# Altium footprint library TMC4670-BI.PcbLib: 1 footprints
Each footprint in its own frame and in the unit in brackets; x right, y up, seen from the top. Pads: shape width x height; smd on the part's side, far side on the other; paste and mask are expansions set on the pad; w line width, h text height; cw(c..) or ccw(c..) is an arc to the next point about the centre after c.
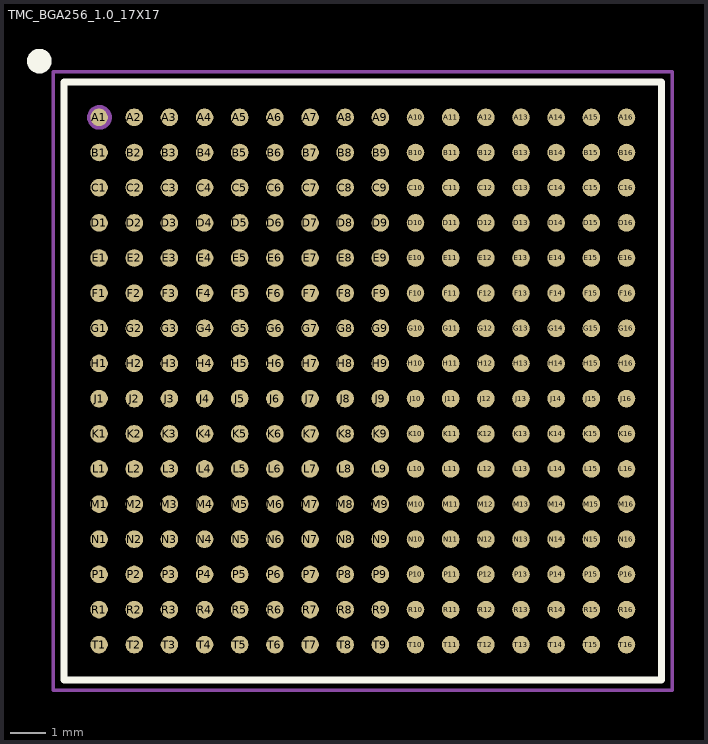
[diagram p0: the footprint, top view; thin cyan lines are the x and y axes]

## TMC_BGA256_1.0_17X17 [mm]
height 2.2
pads (256):
  round 0.5 smd: A1(-1023.5,-1008.5) A2(-1022.5,-1008.5) A3(-1021.5,-1008.5) A4(-1020.5,-1008.5) A5(-1019.5,-1008.5) A6(-1018.5,-1008.5) A7(-1017.5,-1008.5) A8(-1016.5,-1008.5) A9(-1015.5,-1008.5) A10(-1014.5,-1008.5) A11(-1013.5,-1008.5) A12(-1012.5,-1008.5) A13(-1011.5,-1008.5) A14(-1010.5,-1008.5) A15(-1009.5,-1008.5) A16(-1008.5,-1008.5) B1(-1023.5,-1009.5) B2(-1022.5,-1009.5) B3(-1021.5,-1009.5) B4(-1020.5,-1009.5) B5(-1019.5,-1009.5) B6(-1018.5,-1009.5) B7(-1017.5,-1009.5) B8(-1016.5,-1009.5) B9(-1015.5,-1009.5) B10(-1014.5,-1009.5) B11(-1013.5,-1009.5) B12(-1012.5,-1009.5) B13(-1011.5,-1009.5) B14(-1010.5,-1009.5) B15(-1009.5,-1009.5) B16(-1008.5,-1009.5) C1(-1023.5,-1010.5) C2(-1022.5,-1010.5) C3(-1021.5,-1010.5) C4(-1020.5,-1010.5) C5(-1019.5,-1010.5) C6(-1018.5,-1010.5) C7(-1017.5,-1010.5) C8(-1016.5,-1010.5) C9(-1015.5,-1010.5) C10(-1014.5,-1010.5) C11(-1013.5,-1010.5) C12(-1012.5,-1010.5) C13(-1011.5,-1010.5) C14(-1010.5,-1010.5) C15(-1009.5,-1010.5) C16(-1008.5,-1010.5) D1(-1023.5,-1011.5) D2(-1022.5,-1011.5) D3(-1021.5,-1011.5) D4(-1020.5,-1011.5) D5(-1019.5,-1011.5) D6(-1018.5,-1011.5) D7(-1017.5,-1011.5) D8(-1016.5,-1011.5) D9(-1015.5,-1011.5) D10(-1014.5,-1011.5) D11(-1013.5,-1011.5) D12(-1012.5,-1011.5) D13(-1011.5,-1011.5) D14(-1010.5,-1011.5) D15(-1009.5,-1011.5) D16(-1008.5,-1011.5) E1(-1023.5,-1012.5) E2(-1022.5,-1012.5) E3(-1021.5,-1012.5) E4(-1020.5,-1012.5) E5(-1019.5,-1012.5) E6(-1018.5,-1012.5) E7(-1017.5,-1012.5) E8(-1016.5,-1012.5) E9(-1015.5,-1012.5) E10(-1014.5,-1012.5) E11(-1013.5,-1012.5) E12(-1012.5,-1012.5) E13(-1011.5,-1012.5) E14(-1010.5,-1012.5) E15(-1009.5,-1012.5) E16(-1008.5,-1012.5) F1(-1023.5,-1013.5) F2(-1022.5,-1013.5) F3(-1021.5,-1013.5) F4(-1020.5,-1013.5) F5(-1019.5,-1013.5) F6(-1018.5,-1013.5) F7(-1017.5,-1013.5) F8(-1016.5,-1013.5) F9(-1015.5,-1013.5) F10(-1014.5,-1013.5) F11(-1013.5,-1013.5) F12(-1012.5,-1013.5) F13(-1011.5,-1013.5) F14(-1010.5,-1013.5) F15(-1009.5,-1013.5) F16(-1008.5,-1013.5) G1(-1023.5,-1014.5) G2(-1022.5,-1014.5) G3(-1021.5,-1014.5) G4(-1020.5,-1014.5) G5(-1019.5,-1014.5) G6(-1018.5,-1014.5) G7(-1017.5,-1014.5) G8(-1016.5,-1014.5) G9(-1015.5,-1014.5) G10(-1014.5,-1014.5) G11(-1013.5,-1014.5) G12(-1012.5,-1014.5) G13(-1011.5,-1014.5) G14(-1010.5,-1014.5) G15(-1009.5,-1014.5) G16(-1008.5,-1014.5) H1(-1023.5,-1015.5) H2(-1022.5,-1015.5) H3(-1021.5,-1015.5) H4(-1020.5,-1015.5) H5(-1019.5,-1015.5) H6(-1018.5,-1015.5) H7(-1017.5,-1015.5) H8(-1016.5,-1015.5) H9(-1015.5,-1015.5) H10(-1014.5,-1015.5) H11(-1013.5,-1015.5) H12(-1012.5,-1015.5) H13(-1011.5,-1015.5) H14(-1010.5,-1015.5) H15(-1009.5,-1015.5) H16(-1008.5,-1015.5) J1(-1023.5,-1016.5) J2(-1022.5,-1016.5) J3(-1021.5,-1016.5) J4(-1020.5,-1016.5) J5(-1019.5,-1016.5) J6(-1018.5,-1016.5) J7(-1017.5,-1016.5) J8(-1016.5,-1016.5) J9(-1015.5,-1016.5) J10(-1014.5,-1016.5) J11(-1013.5,-1016.5) J12(-1012.5,-1016.5) J13(-1011.5,-1016.5) J14(-1010.5,-1016.5) J15(-1009.5,-1016.5) J16(-1008.5,-1016.5) K1(-1023.5,-1017.5) K2(-1022.5,-1017.5) K3(-1021.5,-1017.5) K4(-1020.5,-1017.5) K5(-1019.5,-1017.5) K6(-1018.5,-1017.5) K7(-1017.5,-1017.5) K8(-1016.5,-1017.5) K9(-1015.5,-1017.5) K10(-1014.5,-1017.5) K11(-1013.5,-1017.5) K12(-1012.5,-1017.5) K13(-1011.5,-1017.5) K14(-1010.5,-1017.5) K15(-1009.5,-1017.5) K16(-1008.5,-1017.5) L1(-1023.5,-1018.5) L2(-1022.5,-1018.5) L3(-1021.5,-1018.5) L4(-1020.5,-1018.5) L5(-1019.5,-1018.5) L6(-1018.5,-1018.5) L7(-1017.5,-1018.5) L8(-1016.5,-1018.5) L9(-1015.5,-1018.5) L10(-1014.5,-1018.5) L11(-1013.5,-1018.5) L12(-1012.5,-1018.5) L13(-1011.5,-1018.5) L14(-1010.5,-1018.5) L15(-1009.5,-1018.5) L16(-1008.5,-1018.5) M1(-1023.5,-1019.5) M2(-1022.5,-1019.5) M3(-1021.5,-1019.5) M4(-1020.5,-1019.5) M5(-1019.5,-1019.5) M6(-1018.5,-1019.5) M7(-1017.5,-1019.5) M8(-1016.5,-1019.5) M9(-1015.5,-1019.5) M10(-1014.5,-1019.5) M11(-1013.5,-1019.5) M12(-1012.5,-1019.5) M13(-1011.5,-1019.5) M14(-1010.5,-1019.5) M15(-1009.5,-1019.5) M16(-1008.5,-1019.5) N1(-1023.5,-1020.5) N2(-1022.5,-1020.5) N3(-1021.5,-1020.5) N4(-1020.5,-1020.5) N5(-1019.5,-1020.5) N6(-1018.5,-1020.5) N7(-1017.5,-1020.5) N8(-1016.5,-1020.5) N9(-1015.5,-1020.5) N10(-1014.5,-1020.5) N11(-1013.5,-1020.5) N12(-1012.5,-1020.5) N13(-1011.5,-1020.5) N14(-1010.5,-1020.5) N15(-1009.5,-1020.5) N16(-1008.5,-1020.5) P1(-1023.5,-1021.5) P2(-1022.5,-1021.5) P3(-1021.5,-1021.5) P4(-1020.5,-1021.5) P5(-1019.5,-1021.5) P6(-1018.5,-1021.5) P7(-1017.5,-1021.5) P8(-1016.5,-1021.5) P9(-1015.5,-1021.5) P10(-1014.5,-1021.5) P11(-1013.5,-1021.5) P12(-1012.5,-1021.5) P13(-1011.5,-1021.5) P14(-1010.5,-1021.5) P15(-1009.5,-1021.5) P16(-1008.5,-1021.5) R1(-1023.5,-1022.5) R2(-1022.5,-1022.5) R3(-1021.5,-1022.5) R4(-1020.5,-1022.5) R5(-1019.5,-1022.5) R6(-1018.5,-1022.5) R7(-1017.5,-1022.5) R8(-1016.5,-1022.5) R9(-1015.5,-1022.5) R10(-1014.5,-1022.5) R11(-1013.5,-1022.5) R12(-1012.5,-1022.5) R13(-1011.5,-1022.5) R14(-1010.5,-1022.5) R15(-1009.5,-1022.5) R16(-1008.5,-1022.5) T1(-1023.5,-1023.5) T2(-1022.5,-1023.5) T3(-1021.5,-1023.5) T4(-1020.5,-1023.5) T5(-1019.5,-1023.5) T6(-1018.5,-1023.5) T7(-1017.5,-1023.5) T8(-1016.5,-1023.5) T9(-1015.5,-1023.5) T10(-1014.5,-1023.5) T11(-1013.5,-1023.5) T12(-1012.5,-1023.5) T13(-1011.5,-1023.5) T14(-1010.5,-1023.5) T15(-1009.5,-1023.5) T16(-1008.5,-1023.5)
Top Overlay:
  circle w0.5: c-1025.2,-1006.9 r0.1
  lines w0.2: -1024.5,-1024.5 -1024.5,-1007.5 -1007.5,-1007.5 -1007.5,-1024.5 -1024.5,-1024.5
Mechanical 1:
  circle w0.5: c-1023.49,-1008.502 r0.1
  lines w0.15: -1024.5,-1024.5 -1007.5,-1024.5 -1007.5,-1007.5 -1024.5,-1007.5 -1024.5,-1024.5
  text "IC1" at -1016.56,-1016.427 h0.6
Mechanical 16:
  lines w0.1: -1024.8,-1024.8 -1007.2,-1024.8 -1007.2,-1007.2 -1024.8,-1007.2 -1024.8,-1024.8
